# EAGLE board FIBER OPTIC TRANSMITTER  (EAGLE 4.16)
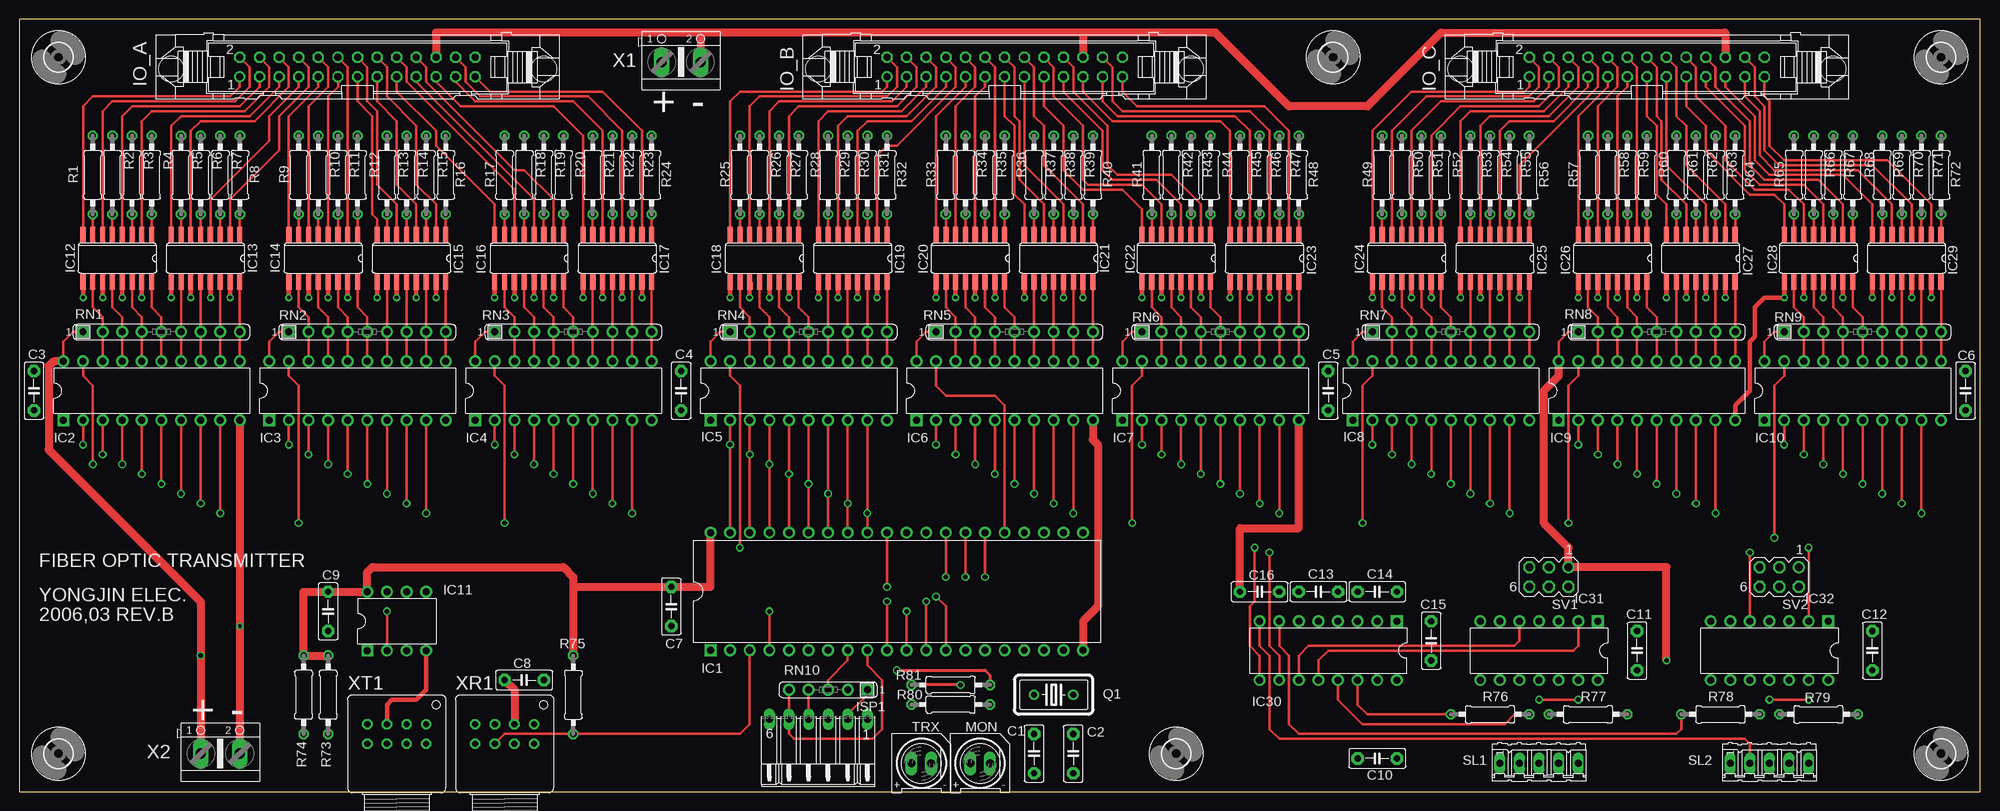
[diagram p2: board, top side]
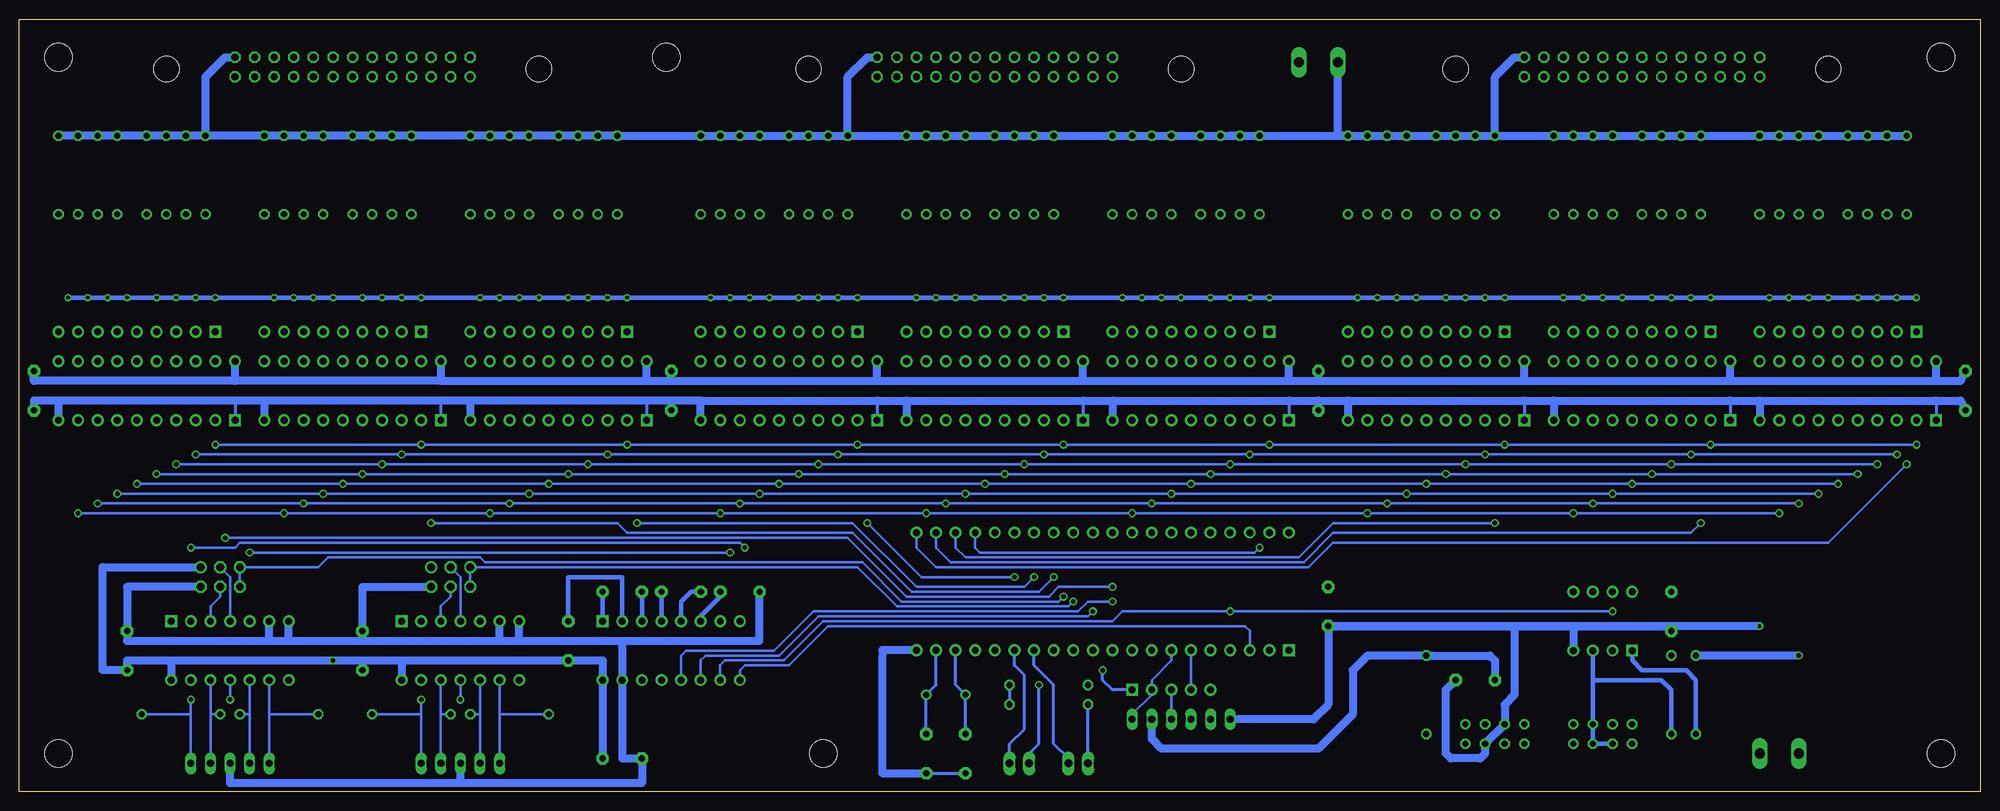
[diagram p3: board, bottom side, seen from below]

Size 253.99 x 100 mm. Coordinates in mm from the lower left corner, seen from the top.
Outline: 0,0 253.99,0 253.99,100 0,100 0,0
Copper layers (1*16): Top 0.035mm / dielectric 1.5mm / Bottom 0.035mm
Design rules "default": minimum track width 10mil, minimum drill 24mil, track to track 8mil, track to pad 8mil, pad to pad 8mil, via to via 8mil, smd to smd 8mil, copper to edge 40mil, drill to drill 8mil, minimum pad ring 10mil, minimum via ring 8mil, stop-mask expansion 4mil, vias tented up to drill 0mil, thermal gap 10mil

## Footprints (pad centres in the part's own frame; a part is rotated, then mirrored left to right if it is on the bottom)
C5B2.5 = drill 0.813 pad 1.6 octagon: 1 -2.54,0; 2 2.54,0
3,6 = hole 3.6: 0,0
DIL40 = drill 0.9 pad 1.524 square: 1 -24.13,-7.62 | drill 0.9 pad 1.524 round: 2 -21.59,-7.62; 3 -19.05,-7.62; 4 -16.51,-7.62; 5 -13.97,-7.62; 6 -11.43,-7.62; 7 -8.89,-7.62; 8 -6.35,-7.62; 9 -3.81,-7.62; 10 -1.27,-7.62; 11 1.27,-7.62; 12 3.81,-7.62; 13 6.35,-7.62; 14 8.89,-7.62; 15 11.43,-7.62; 16 13.97,-7.62; 17 16.51,-7.62; 18 19.05,-7.62; 19 21.59,-7.62; 20 24.13,-7.62; 21 24.13,7.62; 22 21.59,7.62; 23 19.05,7.62; 24 16.51,7.62; 25 13.97,7.62; 26 11.43,7.62; 27 8.89,7.62; 28 6.35,7.62; 29 3.81,7.62; 30 1.27,7.62; 31 -1.27,7.62; 32 -3.81,7.62; 33 -6.35,7.62; 34 -8.89,7.62; 35 -11.43,7.62; 36 -13.97,7.62; 37 -16.51,7.62; 38 -19.05,7.62; 39 -21.59,7.62; 40 -24.13,7.62
DIL20 = drill 0.9 pad 1.524 square: 1 -11.43,-3.81 | drill 0.9 pad 1.524 round: 2 -8.89,-3.81; 3 -6.35,-3.81; 4 -3.81,-3.81; 5 -1.27,-3.81; 6 1.27,-3.81; 7 3.81,-3.81; 8 6.35,-3.81; 9 8.89,-3.81; 10 11.43,-3.81; 11 11.43,3.81; 12 8.89,3.81; 13 6.35,3.81; 14 3.81,3.81; 15 1.27,3.81; 16 -1.27,3.81; 17 -3.81,3.81; 18 -6.35,3.81; 19 -8.89,3.81; 20 -11.43,3.81
DIL08 = drill 0.9 pad 1.524 square: 1 -3.81,-5.08 | drill 0.9 pad 1.524 round: 2 -1.27,-5.08; 3 1.27,-5.08; 4 3.81,-5.08; 5 3.81,2.54; 6 1.27,2.54; 7 -1.27,2.54; 8 -3.81,2.54
SOIC16 = smd 0.66 x 2.032: 1 -4.445,-3.073; 2 -3.175,-3.073; 3 -1.905,-3.073; 4 -0.635,-3.073; 5 0.635,-3.073; 6 1.905,-3.073; 7 3.175,-3.073; 8 4.445,-3.073; 9 4.445,3.073; 10 3.175,3.073; 11 1.905,3.073; 12 0.635,3.073; 13 -0.635,3.073; 14 -1.905,3.073; 15 -3.175,3.073; 16 -4.445,3.073
DIL16 = drill 0.9 pad 1.524 square: 1 -8.89,-3.81 | drill 0.9 pad 1.524 round: 2 -6.35,-3.81; 3 -3.81,-3.81; 4 -1.27,-3.81; 5 1.27,-3.81; 6 3.81,-3.81; 7 6.35,-3.81; 8 8.89,-3.81; 9 8.89,3.81; 10 6.35,3.81; 11 3.81,3.81; 12 1.27,3.81; 13 -1.27,3.81; 14 -3.81,3.81; 15 -6.35,3.81; 16 -8.89,3.81
DIL14 = drill 0.9 pad 1.524 square: 1 -7.62,-3.81 | drill 0.9 pad 1.524 round: 2 -5.08,-3.81; 3 -2.54,-3.81; 4 0,-3.81; 5 2.54,-3.81; 6 5.08,-3.81; 7 7.62,-3.81; 8 7.62,3.81; 9 5.08,3.81; 10 2.54,3.81; 11 0,3.81; 12 -2.54,3.81; 13 -5.08,3.81; 14 -7.62,3.81
26V = drill 0.914 round: 1 -15.24,-1.27 | drill 0.914 octagon: 2 -15.24,1.27; 3 -12.7,-1.27; 4 -12.7,1.27; 5 -10.16,-1.27; 6 -10.16,1.27; 7 -7.62,-1.27; 8 -7.62,1.27; 9 -5.08,-1.27; 10 -5.08,1.27; 11 -2.54,-1.27; 12 -2.54,1.27; 13 0,-1.27; 14 0,1.27; 15 2.54,-1.27; 16 2.54,1.27; 17 5.08,-1.27; 18 5.08,1.27; 19 7.62,-1.27; 20 7.62,1.27; 21 10.16,-1.27; 22 10.16,1.27; 23 12.7,-1.27; 24 12.7,1.27; 25 15.24,-1.27; 26 15.24,1.27 | hole 3.302: 24.13,-0.254; -24.13,-0.254
06PA = drill 0.914 long: 1 -6.35,0; 2 -3.81,0; 3 -1.27,0; 4 1.27,0; 5 3.81,0; 6 6.35,0
Q62902-B156 = drill 1.016 long: A -1.27,0; K 1.27,0
HC18U-V = drill 0.813 round: 1 -2.54,0; 2 2.54,0
0207/10 = drill 0.813 octagon: 1 -5.08,0; 2 5.08,0
SIL9 = drill 0.9 pad 1.524 square: 1 -10.16,0 | drill 0.9 pad 1.524 round: 2 -7.62,0; 3 -5.08,0; 4 -2.54,0; 5 0,0; 6 2.54,0; 7 5.08,0; 8 7.62,0; 9 10.16,0
SIL5 = drill 0.9 pad 1.524 square: 1 -5.08,0 | drill 0.9 pad 1.524 round: 2 -2.54,0; 3 0,0; 4 2.54,0; 5 5.08,0
05P = drill 0.914 long: 1 -5.08,0; 2 -2.54,0; 3 0,0; 4 2.54,0; 5 5.08,0
MA03-2 = drill 1.016 round: 1 -2.54,-1.27 | drill 1.016 octagon: 2 -2.54,1.27; 3 0,-1.27; 4 0,1.27; 5 2.54,-1.27; 6 2.54,1.27
AK500/2 = drill 1.321 long: 1 -2.515,0; 2 2.515,0
HFBR-X41XT = drill 0.813 round: 1 3.81,2.54 | drill 0.813 octagon: 2 1.27,2.54; 3 -1.27,2.54; 4 -3.81,2.54; 5 -3.81,0; 6 -1.27,0; 7 1.27,0; 8 3.81,0

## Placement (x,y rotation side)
C1  [C5B2.5]  131.44,4.92 90 top
C2  [C5B2.5]  136.52,4.92 90 top
C3  [C5B2.5]  1.9,51.91 270 top
C4  [C5B2.5]  85.72,51.91 270 top
C5  [C5B2.5]  169.54,51.91 270 top
C6  [C5B2.5]  252.09,51.91 270 top
C7  [C5B2.5]  84.45,23.96 270 top
C8  [C5B2.5]  65.4,14.44 0 top
C9  [C5B2.5]  40,23.33 270 top
C10  [C5B2.5]  175.89,4.28 180 top
C11  [C5B2.5]  209.55,18.25 90 top
C12  [C5B2.5]  240.03,18.25 90 top
C13  [C5B2.5]  168.27,25.87 180 top
C14  [C5B2.5]  175.89,25.87 180 top
C15  [C5B2.5]  182.88,19.52 270 top
C16  [C5B2.5]  160.65,25.87 0 top
H1  MOUNT-HOLE3.6  [3,6]  5.08,4.92 0 top
H2  MOUNT-HOLE3.6  [3,6]  5.08,95.08 0 top
H3  MOUNT-HOLE3.6  [3,6]  149.86,4.92 0 top
H4  MOUNT-HOLE3.6  [3,6]  170.18,95.08 0 top
H5  MOUNT-HOLE3.6  [3,6]  248.91,4.92 0 top
H6  MOUNT-HOLE3.6  [3,6]  248.91,95.08 0 top
IC1  MEGA161P  [DIL40]  113.66,25.92 0 top
IC2  74HC245N  [DIL20]  17.14,51.91 0 top
IC3  74HC245N  [DIL20]  43.81,51.91 0 top
IC4  74HC245N  [DIL20]  70.48,51.91 0 top
IC5  74HC245N  [DIL20]  100.96,51.91 0 top
IC6  74HC245N  [DIL20]  127.63,51.91 0 top
IC7  74HC245N  [DIL20]  154.3,51.91 0 top
IC8  74HC245N  [DIL20]  184.15,51.91 0 top
IC9  74HC245N  [DIL20]  210.81,51.91 0 top
IC10  74HC245N  [DIL20]  237.49,51.91 0 top
IC11  75452  [DIL08]  48.89,23.33 0 top
IC12  TCMT4100  [SOIC16]  12.69,69.05 180 top
IC13  TCMT4100  [SOIC16]  24.12,69.05 180 top
IC14  TCMT4100  [SOIC16]  39.36,69.05 180 top
IC15  TCMT4100  [SOIC16]  50.79,69.05 180 top
IC16  TCMT4100  [SOIC16]  66.04,69.05 180 top
IC17  TCMT4100  [SOIC16]  77.47,69.05 180 top
IC18  TCMT4100  [SOIC16]  96.52,69.05 180.1 top
IC19  TCMT4100  [SOIC16]  107.95,69.05 180 top
IC20  TCMT4100  [SOIC16]  123.19,69.05 180 top
IC21  TCMT4100  [SOIC16]  134.62,69.05 180 top
IC22  TCMT4100  [SOIC16]  149.86,69.05 180 top
IC23  TCMT4100  [SOIC16]  161.28,69.05 180 top
IC24  TCMT4100  [SOIC16]  179.7,69.05 180 top
IC25  TCMT4100  [SOIC16]  191.13,69.05 180 top
IC26  TCMT4100  [SOIC16]  206.37,69.05 180 top
IC27  TCMT4100  [SOIC16]  217.8,69.05 180 top
IC28  TCMT4100  [SOIC16]  233.04,69.05 180 top
IC29  TCMT4100  [SOIC16]  244.47,69.05 180 top
IC30  MAX232  [DIL16]  169.54,18.25 180 top
IC31  MAX489CPD  [DIL14]  196.84,18.25 180 top
IC32  MAX489CPD  [DIL14]  226.69,18.25 180 top
IO_A  [26V]  43.81,93.81 0 top
IO_B  [26V]  127.63,93.81 0 top
IO_C  [26V]  210.81,93.81 0 top
ISP1  [06PA]  103.5,9.36 180 top
MON  [Q62902-B156]  124.45,3.65 0 top
Q1  [HC18U-V]  133.98,12.54 180 top
R1  [0207/10]  9.52,79.84 270 top
R2  [0207/10]  12.06,79.84 270 top
R3  [0207/10]  14.6,79.84 270 top
R4  [0207/10]  17.14,79.84 270 top
R5  [0207/10]  20.95,79.84 270 top
R6  [0207/10]  23.49,79.84 270 top
R7  [0207/10]  26.03,79.84 270 top
R8  [0207/10]  28.57,79.84 270 top
R9  [0207/10]  36.19,79.84 270 top
R10  [0207/10]  38.73,79.84 270 top
R11  [0207/10]  41.27,79.84 270 top
R12  [0207/10]  43.81,79.84 270 top
R13  [0207/10]  47.62,79.84 270 top
R14  [0207/10]  50.16,79.84 270 top
R15  [0207/10]  52.7,79.84 270 top
R16  [0207/10]  55.24,79.84 270 top
R17  [0207/10]  62.86,79.84 270 top
R18  [0207/10]  65.4,79.84 270 top
R19  [0207/10]  67.94,79.84 270 top
R20  [0207/10]  70.48,79.84 270 top
R21  [0207/10]  74.29,79.84 270 top
R22  [0207/10]  76.83,79.84 270 top
R23  [0207/10]  79.37,79.84 270 top
R24  [0207/10]  81.91,79.84 270 top
R25  [0207/10]  93.34,79.84 270 top
R26  [0207/10]  95.88,79.84 270 top
R27  [0207/10]  98.42,79.84 270 top
R28  [0207/10]  100.96,79.84 270 top
R29  [0207/10]  104.77,79.84 270 top
R30  [0207/10]  107.31,79.84 270 top
R31  [0207/10]  109.85,79.84 270 top
R32  [0207/10]  112.39,79.84 270 top
R33  [0207/10]  120.01,79.84 270 top
R34  [0207/10]  122.55,79.84 270 top
R35  [0207/10]  125.09,79.84 270 top
R36  [0207/10]  127.63,79.84 270 top
R37  [0207/10]  131.44,79.84 270 top
R38  [0207/10]  133.98,79.84 270 top
R39  [0207/10]  136.52,79.84 270 top
R40  [0207/10]  139.06,79.84 270 top
R41  [0207/10]  146.68,79.84 270 top
R42  [0207/10]  149.22,79.84 270 top
R43  [0207/10]  151.76,79.84 270 top
R44  [0207/10]  154.3,79.84 270 top
R45  [0207/10]  158.11,79.84 270 top
R46  [0207/10]  160.65,79.84 270 top
R47  [0207/10]  163.19,79.84 270 top
R48  [0207/10]  165.73,79.84 270 top
R49  [0207/10]  176.53,79.84 270 top
R50  [0207/10]  179.06,79.84 270 top
R51  [0207/10]  181.61,79.84 270 top
R52  [0207/10]  184.15,79.84 270 top
R53  [0207/10]  187.96,79.84 270 top
R54  [0207/10]  190.5,79.84 270 top
R55  [0207/10]  193.03,79.84 270 top
R56  [0207/10]  195.58,79.84 270 top
R57  [0207/10]  203.19,79.84 270 top
R58  [0207/10]  205.74,79.84 270 top
R59  [0207/10]  208.28,79.84 270 top
R60  [0207/10]  210.81,79.84 270 top
R61  [0207/10]  214.62,79.84 270 top
R62  [0207/10]  217.16,79.84 270 top
R63  [0207/10]  219.71,79.84 270 top
R64  [0207/10]  222.25,79.84 270 top
R65  [0207/10]  229.87,79.84 270 top
R66  [0207/10]  232.41,79.84 270 top
R67  [0207/10]  234.94,79.84 270 top
R68  [0207/10]  237.49,79.84 270 top
R69  [0207/10]  241.3,79.84 270 top
R70  [0207/10]  243.84,79.84 270 top
R71  [0207/10]  246.38,79.84 270 top
R72  [0207/10]  248.91,79.84 270 top
R73  [0207/10]  40,12.54 90 top
R74  [0207/10]  36.82,12.54 90 top
R75  [0207/10]  71.75,12.54 270 top
R76  [0207/10]  190.5,10 180 top
R77  [0207/10]  203.19,10 180 top
R78  [0207/10]  220.34,10 180 top
R79  [0207/10]  233.04,10 180 top
R80  [0207/10]  120.65,11.27 0 top
R81  [0207/10]  120.65,13.81 0 top
RN1  [SIL9]  18.41,59.52 0 top
RN2  [SIL9]  45.08,59.52 0 top
RN3  [SIL9]  71.75,59.52 0 top
RN4  [SIL9]  102.23,59.52 0 top
RN5  [SIL9]  128.9,59.52 0 top
RN6  [SIL9]  155.57,59.52 0 top
RN7  [SIL9]  185.41,59.52 0 top
RN8  [SIL9]  212.09,59.52 0 top
RN9  [SIL9]  238.75,59.52 0 top
RN10  [SIL5]  104.77,13.17 180 top
SL1  [05P]  196.84,3.65 0 top
SL2  [05P]  226.69,3.65 0 top
SV1  [MA03-2]  198.12,27.78 180 top
SV2  [MA03-2]  227.96,27.78 180 top
TRX  [Q62902-B156]  116.84,3.65 0 top
X1  [AK500/2]  85.72,94.45 0 top
X2  [AK500/2]  26.03,4.92 0 top
XR1  2412T  [HFBR-X41XT]  62.86,6.18 0 top
XT1  1412T  [HFBR-X41XT]  48.89,6.18 0 top

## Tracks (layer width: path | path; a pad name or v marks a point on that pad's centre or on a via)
+12V
  Bottom 1.016: R1.1 R2.1 R3.1 R4.1 R5.1 R6.1 R7.1 R8.1 R9.1 R10.1 R11.1 R12.1 R13.1 R14.1 R15.1 R16.1 R17.1 | R19.1 R18.1 | R20.1 R19.1 | R21.1 R20.1 | R22.1 R21.1 | R23.1 R22.1 | R24.1 R23.1 | R18.1 R17.1 | R18.1 R17.1 | R19.1 R18.1 | R20.1 R19.1 | R21.1 R20.1 | R22.1 R21.1 | R23.1 R22.1 | R24.1 R23.1 | R25.1 R24.1 | R26.1 R25.1 | 96.52,84.92 R26.1 | 96.52,84.92 97.15,84.92 | R27.1 96.52,84.92 | R27.1 R26.1 | R27.1 R28.1 R29.1 R30.1 R31.1 R32.1 | R27.1 R25.1 | R32.1 113.03,84.92 | R32.1 R33.1 R34.1 R35.1 R36.1 R37.1 R38.1 R39.1 R40.1 R41.1 | R41.1 R42.1 R43.1 R44.1 R45.1 R46.1 R47.1 R48.1 R49.1 R50.1 R51.1 R52.1 R53.1 R54.1 R55.1 R56.1 R57.1 R58.1 R59.1 R60.1 R61.1 R62.1 R63.1 R64.1 R65.1 | R65.1 R66.1 R67.1 R68.1 R69.1 R70.1 R71.1 R72.1 | IO_C.26 227.33,95.08 229.87,92.54 R65.1 | IO_A.26 60.32,95.08 62.86,92.54 R17.1 | IO_B.26 144.14,95.08 146.68,92.54 R41.1 | X1.1 83.18,84.9 R24.1
-12V
  Top 1.016: IO_C.22 220.97,98.26 184.15,98.26 174.62,88.73 164.46,88.73 154.94,98.26 137.79,98.26 | 137.79,98.26 IO_B.22 | 137.79,98.26 88.26,98.26 | 88.26,98.26 53.97,98.26 IO_A.22 | X1.2 88.26,94.47 88.26,98.26
/RST
  Top 0.305: RN10.5 ISP1.5 99.69,7.46 100.33,6.82 110.48,6.82 111.76,8.09 111.76,14.44 109.85,16.35 IC1.9
BD0  (via drill 0.6)
  Top 0.305: v8.25,44.92 IC2.2 | v34.92,44.92 IC3.2 | v34.92,44.92 IC3.2 | v228.59,44.92 IC10.2 | v34.92,44.92 IC3.2 | v61.59,44.92 IC4.2 | IC1.39 v92.07,44.92 IC5.2 | v145.41,44.92 IC7.2 | v175.25,44.92 IC8.2 | v201.93,44.92 IC9.2 | v118.74,44.92 IC6.2 v118.74,44.92
  Bottom 0.305: v8.25,44.92 v34.92,44.92 v61.59,44.92 v92.07,44.92 | v228.59,44.92 v201.93,44.92 v175.25,44.92 v145.41,44.92 v118.74,44.92 | v118.74,44.92 v92.07,44.92 | v118.74,44.92 v92.07,44.92
BD1  (via drill 0.6)
  Top 0.305: v10.79,43.65 IC2.3 | v37.46,43.65 IC3.3 | v231.13,43.65 IC10.3 | v64.13,43.65 IC4.3 | IC5.3 v94.61,43.65 IC1.38 | v147.95,43.65 IC7.3 | v177.8,43.65 IC8.3 | v204.47,43.65 IC9.3 | v121.28,43.65 IC6.3 v121.28,43.65
  Bottom 0.305: v37.46,43.65 v10.79,43.65 | v231.13,43.65 v204.47,43.65 v177.8,43.65 v147.95,43.65 v121.28,43.65 | v94.61,43.65 v64.13,43.65 | v64.13,43.65 v37.46,43.65 | v64.13,43.65 v37.46,43.65 | v121.28,43.65 v94.61,43.65 | v121.28,43.65 v94.61,43.65
BD2  (via drill 0.6)
  Top 0.305: v13.33,42.38 IC2.4 | v40,42.38 IC3.4 | v233.68,42.38 IC10.4 | v66.67,42.38 IC4.4 | IC5.4 v97.15,42.38 IC1.37 | v123.82,42.38 IC6.4 | v150.49,42.38 IC7.4 | v180.34,42.38 IC8.4 | IC9.4 v207,42.38
  Bottom 0.305: v40,42.38 v13.33,42.38 | v233.68,42.38 v207,42.38 v180.34,42.38 v150.49,42.38 | v66.67,42.38 v97.15,42.38 v123.82,42.38 | v66.67,42.38 v40,42.38 | v66.67,42.38 v40,42.38 | v150.49,42.38 v123.82,42.38 | v150.49,42.38 v123.82,42.38
BD3  (via drill 0.6)
  Top 0.305: v15.87,41.11 IC2.5 | v42.54,41.11 IC3.5 | IC5.5 v99.69,41.11 IC1.36 | v236.22,41.11 IC10.5 | v126.36,41.11 IC6.5 | v153.03,41.11 IC7.5 | v182.88,41.11 IC8.5 | IC9.5 v209.55,41.11 | v69.21,41.11 IC4.5 v69.21,41.11
  Bottom 0.305: v15.87,41.11 v42.54,41.11 v69.21,41.11 v99.69,41.11 v126.36,41.11 | v236.22,41.11 v209.55,41.11 v182.88,41.11 v153.03,41.11 | v153.03,41.11 v126.36,41.11 | v153.03,41.11 v126.36,41.11
BD4  (via drill 0.6)
  Top 0.305: v18.41,39.84 IC2.6 | v45.08,39.84 IC3.6 | v102.23,39.84 IC1.35 | v102.23,39.84 IC5.6 v102.23,39.84 | IC1.35 102.23,33.49 | v102.23,39.84 IC1.35 | IC9.6 v212.09,39.84 | v238.75,39.84 IC10.6 | v71.75,39.84 IC4.6 v71.75,39.84 | v128.9,39.84 IC6.6 v128.9,39.84 | v155.57,39.84 IC7.6 v155.57,39.84 | v185.41,39.84 IC8.6 v185.41,39.84
  Bottom 0.305: v18.41,39.84 v45.08,39.84 v71.75,39.84 v102.23,39.84 v128.9,39.84 v155.57,39.84 v185.41,39.84 v212.09,39.84 v238.75,39.84
BD5  (via drill 0.6)
  Top 0.305: v20.95,38.57 IC2.7 | v47.62,38.57 IC3.7 | v104.77,38.57 IC1.34 | v104.77,38.57 IC5.7 v104.77,38.57 | IC1.34 104.77,33.49 | v104.77,38.57 IC1.34 | IC9.7 v214.62,38.57 | v241.3,38.57 IC10.7 | v74.29,38.57 IC4.7 v74.29,38.57 | v131.44,38.57 IC6.7 v131.44,38.57 | v158.11,38.57 IC7.7 v158.11,38.57 | v187.96,38.57 IC8.7 v187.96,38.57
  Bottom 0.305: v20.95,38.57 v47.62,38.57 v74.29,38.57 v104.77,38.57 v131.44,38.57 v158.11,38.57 v187.96,38.57 v214.62,38.57 v241.3,38.57
BD6  (via drill 0.6)
  Top 0.305: v23.49,37.3 IC2.8 | v76.83,37.3 IC4.8 | v76.83,37.3 IC4.8 | v107.31,37.3 IC1.33 | v107.31,37.3 IC5.8 v107.31,37.3 | v76.83,37.3 IC4.8 | IC1.33 107.31,33.49 | v107.31,37.3 IC1.33 | IC9.8 v217.16,37.3 | v243.84,37.3 IC10.8 | v50.16,37.3 IC3.8 v50.16,37.3 | v133.98,37.3 IC6.8 v133.98,37.3 | v160.65,37.3 IC7.8 v160.65,37.3 | v190.5,37.3 IC8.8 v190.5,37.3
  Bottom 0.305: v23.49,37.3 v50.16,37.3 v76.83,37.3 v107.31,37.3 v133.98,37.3 v160.65,37.3 v190.5,37.3 v217.16,37.3 v243.84,37.3 | IC1.33 107.31,33.49
BD7  (via drill 0.6)
  Top 0.305: v26.03,36.03 IC2.9 | v109.85,36.03 IC1.32 | v109.85,36.03 IC5.9 v109.85,36.03 | IC1.32 109.85,33.49 | v109.85,36.03 IC1.32 | v219.71,36.03 IC9.9 | v246.38,36.03 IC10.9 | v52.7,36.03 IC3.9 v52.7,36.03 | v79.37,36.03 IC4.9 v79.37,36.03 | v136.52,36.03 IC6.9 v136.52,36.03 | v163.19,36.03 IC7.9 v163.19,36.03 | v193.03,36.03 IC8.9 v193.03,36.03
  Bottom 0.305: v26.03,36.03 v52.7,36.03 v79.37,36.03 v109.85,36.03 v136.52,36.03 v163.19,36.03 v193.03,36.03 v219.71,36.03 v246.38,36.03
GND5  (via drill 0.5)
  Top 0.61: XT1.3 47.62,11.27 48.25,11.9 51.43,11.9 52.7,13.17 IC11.4 | v8.25,63.97 IC12.9 | v10.79,63.97 IC12.11 | v13.33,63.97 IC12.13 | v15.87,63.97 IC12.15 | v19.68,63.97 IC13.9 | v22.22,63.97 IC13.11 | v24.76,63.97 IC13.13 | v27.3,63.97 IC13.15 | v34.92,63.97 IC14.9 | v37.46,63.97 IC14.11 | v40,63.97 IC14.13 | v42.54,63.97 IC14.15 | v46.35,63.97 IC15.9 | v48.89,63.97 IC15.11 | v51.43,63.97 IC15.13 | v53.97,63.97 IC15.15 | v61.59,63.97 IC16.9 | v64.13,63.97 IC16.11 | v66.67,63.97 IC16.13 | v69.21,63.97 IC16.15 | v73.02,63.97 IC17.9 | v75.56,63.97 IC17.11 | v78.1,63.97 IC17.13 | v80.64,63.97 IC17.15 | v103.5,63.97 IC19.9 | v106.04,63.97 IC19.11 | v108.58,63.97 IC19.13 | v111.12,63.97 IC19.15 | v118.74,63.97 IC20.9 | v121.28,63.97 IC20.11 | v123.82,63.97 IC20.13 | v126.36,63.97 IC20.15 | v130.17,63.97 IC21.9 | v132.71,63.97 IC21.11 | v135.25,63.97 IC21.13 | v137.79,63.97 IC21.15 | v145.41,63.97 IC22.9 | v147.95,63.97 IC22.11 | v150.49,63.97 IC22.13 | v153.03,63.97 IC22.15 | v156.84,63.97 IC23.9 | v159.38,63.97 IC23.11 | v161.92,63.97 IC23.13 | v164.46,63.97 IC23.15 | v175.25,63.97 IC24.9 | v177.8,63.97 IC24.11 | v180.34,63.97 IC24.13 | v182.88,63.97 IC24.15 | v186.69,63.97 IC25.9 | v189.22,63.97 IC25.11 | v191.77,63.97 IC25.13 | v194.31,63.97 IC25.15 | v201.93,63.97 IC26.9 | v204.47,63.97 IC26.11 | v207,63.97 IC26.13 | v209.55,63.97 IC26.15 | v213.36,63.97 IC27.9 | v215.9,63.97 IC27.11 | v218.44,63.97 IC27.13 | v220.97,63.97 IC27.15 | IC28.9 v228.59,63.97 226.06,63.97 224.78,62.7 224.78,58.89 224.15,58.26 224.15,51.91 222.25,50 IC9.10 | v231.13,63.97 IC28.11 | v233.68,63.97 IC28.13 | v236.22,63.97 IC28.15 | v240.03,63.97 IC29.9 | v242.56,63.97 IC29.11 | v245.11,63.97 IC29.13 | v247.65,63.97 IC29.15
  Top 0.61: 92.07,65.88 92.08,65.88 IC18.9 v92.08,63.98 v92.07,63.97 92.07,65.88 | 94.61,65.88 94.62,65.88 IC18.11 v94.62,63.98 v94.61,63.97 94.61,65.88 | 97.15,65.88 97.16,65.88 IC18.13 v97.16,63.98 v97.15,63.97 97.15,65.88 | 99.69,65.88 99.7,65.88 IC18.15 v99.7,63.98 v99.69,63.97 99.69,65.88
  Top 1.016: IC2.10 v28.57,21.43 28.57,4.92 X2.2 | IC6.10 139.06,45.55 139.69,44.92 139.69,23.96 137.79,22.06 IC1.20 137.79,18.25 | C16.1 158.11,34.12 165.73,34.12 IC7.10
  Bottom 0.406: C2.1 C1.1 | 226.06,50.63 IC10.1 | 199.38,50.63 IC9.1 | 172.72,50.63 IC8.1 | 142.87,50.63 IC7.1 | 116.2,50.63 IC6.1 | 89.53,50.63 IC5.1 | 59.05,50.63 IC4.1 | 32.38,50.63 IC3.1 | 5.71,50.63 IC2.1
  Bottom 0.61: v8.25,63.97 v10.79,63.97 v13.33,63.97 v15.87,63.97 v19.68,63.97 v22.22,63.97 v24.76,63.97 v27.3,63.97 v34.92,63.97 v37.46,63.97 v40,63.97 v42.54,63.97 v46.35,63.97 v48.89,63.97 v51.43,63.97 v53.97,63.97 v61.59,63.97 v64.13,63.97 v66.67,63.97 v69.21,63.97 v73.02,63.97 v75.56,63.97 v78.1,63.97 v80.64,63.97 v92.07,63.97 v94.61,63.97 v97.15,63.97 v99.69,63.97 v103.5,63.97 v106.04,63.97 v108.58,63.97 v111.12,63.97 v118.74,63.97 v121.28,63.97 v123.82,63.97 v126.36,63.97 v130.17,63.97 v132.71,63.97 v135.25,63.97 v137.79,63.97 v145.41,63.97 v147.95,63.97 v150.49,63.97 v153.03,63.97 v156.84,63.97 v159.38,63.97 v161.92,63.97 v164.46,63.97 v175.25,63.97 v177.8,63.97 v180.34,63.97 v182.88,63.97 v186.69,63.97 v189.22,63.97 v191.77,63.97 v194.31,63.97 v201.93,63.97 v204.47,63.97 v207,63.97 v209.55,63.97 v213.36,63.97 v215.9,63.97 v218.44,63.97 v220.97,63.97 v228.59,63.97 v231.13,63.97 v233.68,63.97 v236.22,63.97 v240.03,63.97 v242.56,63.97 v245.11,63.97 v247.65,63.97 | 186.05,50.63 199.38,50.63 221.61,50.63 222.25,50
  Bottom 1.016: 52.7,21.43 40,21.43 C9.2 | 60.32,21.43 52.7,21.43 | C7.2 60.32,21.43 | C7.2 84.45,11.27 86.36,9.36 ISP1.6 | 52.7,21.43 IC11.4 | 60.32,21.43 60.32,12.54 61.59,11.27 XR1.3 XR1.7 64.13,4.92 64.77,4.28 68.58,4.28 69.21,4.92 69.21,13.17 C8.2 | C6.2 252.09,50.63 248.91,50.63 | 248.91,50.63 IC10.10 | 222.25,50.63 226.06,50.63 248.91,50.63 | IC9.10 222.25,50 222.25,50.63 | 195.58,50.63 199.38,50.63 222.25,50.63 | 195.58,50.63 IC8.10 | 195.58,50.63 186.05,50.63 172.72,50.63 169.54,50.63 | 169.54,50.63 C5.2 | 165.73,50.63 169.54,50.63 | IC7.10 165.73,50.63 | 165.73,50.63 142.87,50.63 139.06,50.63 | 139.06,50.63 IC6.10 | 139.06,50.63 116.2,50.63 112.39,50.63 | 112.39,50.63 IC5.10 | 112.39,50.63 89.53,50.63 85.72,50.63 | 85.72,50.63 C4.2 | 85.72,50.63 81.91,50.63 | 81.91,50.63 IC4.10 | 81.91,50.63 59.05,50.63 55.24,50.63 | 55.24,50.63 IC3.10 | 28.57,50.63 IC2.10 | 55.24,50.63 32.38,50.63 28.57,50.63 | C3.2 2.54,50.63 5.71,50.63 28.57,50.63 | v28.57,21.43 C7.2 | IC1.20 142.19,18.3 142.24,16.98 142.24,2.38 C2.1 | 221.61,19.52 240.03,19.52 C12.2 240.03,26.51 SV2.2 | 221.61,19.52 IC32.6 | 175.89,19.52 IC30.15 175.89,4.28 C10.2 173.35,1.1 196.84,1.1 | 189.22,19.52 175.89,19.52 | 189.22,19.52 IC31.7 | 191.77,19.52 189.22,19.52 | 191.77,19.52 IC31.6 | 209.55,19.52 191.77,19.52 | 209.55,19.52 C11.2 209.55,26.51 SV1.2 | 219.07,19.52 209.55,19.52 | 219.07,19.52 IC32.7 | 221.61,19.52 219.07,19.52 | 196.84,1.1 SL1.3 | SL2.3 226.69,1.1 196.84,1.1 | C16.1 158.11,19.52 175.89,19.52
I_A0
  Top 0.305: IC12.8 8.25,88.73 9.52,90 27.3,90 28.57,91.27 IO_A.1
I_A1
  Top 0.305: IC12.6 10.79,88.1 12.06,89.37 27.94,89.37 29.84,91.27 29.84,93.81 IO_A.2
I_A2
  Top 0.305: IC12.4 13.33,87.46 14.6,88.73 28.57,88.73 31.11,91.27 IO_A.3
I_A3
  Top 0.305: IC12.2 15.87,86.83 17.14,88.1 29.21,88.1 32.38,91.27 32.38,93.81 IO_A.4
I_A4
  Top 0.305: IC13.8 19.68,86.19 20.95,87.46 29.84,87.46 33.65,91.27 IO_A.5
I_A5
  Top 0.305: IC13.6 22.22,85.56 23.49,86.83 30.48,86.83 34.92,91.27 34.92,93.81 IO_A.6
I_A6
  Top 0.305: IC13.4 24.76,76.67 32.38,84.29 32.38,87.46 36.19,91.27 IO_A.7
I_A7
  Top 0.305: IC13.2 27.3,76.67 33.65,83.02 33.65,87.46 37.46,91.27 37.46,93.81 IO_A.8
I_A8
  Top 0.305: IC14.8 34.92,87.46 38.73,91.27 IO_A.9
I_A9
  Top 0.305: IC14.6 37.46,88.73 40,91.27 40,93.81 IO_A.10
I_A10
  Top 0.305: IC14.4 40,90 41.27,91.27 IO_A.11
I_A11
  Top 0.305: IC14.2 42.54,93.81 IO_A.12
I_A12
  Top 0.305: IC15.8 46.35,74.13 45.71,74.77 45.71,87.46 43.81,89.37 IO_A.13
I_A13
  Top 0.305: IC15.6 48.89,76.03 46.35,78.57 46.35,88.1 45.08,89.37 45.08,93.81 IO_A.14
I_A14
  Top 0.305: IC15.4 51.43,76.03 48.89,78.57 48.89,86.83 46.35,89.37 IO_A.15
I_A15
  Top 0.305: IC15.2 53.97,76.03 51.43,78.57 51.43,86.19 47.62,90 47.62,93.81 IO_A.16
I_A16
  Top 0.305: IC16.8 61.59,76.03 53.97,83.65 53.97,85.56 48.89,90.64 IO_A.17
I_A17
  Top 0.305: IC16.6 64.13,77.94 50.16,91.91 50.16,93.81 IO_A.18
I_A18
  Top 0.305: IC16.4 66.67,76.67 51.43,91.91 IO_A.19
I_A19
  Top 0.305: IC16.2 69.21,76.67 65.4,80.48 64.13,80.48 52.7,91.91 52.7,93.81 IO_A.20
I_A20
  Top 0.305: IC17.8 73.02,84.92 69.21,88.73 57.14,88.73 53.97,91.91 IO_A.21
I_A21
  Top 0.305: IC17.6 75.56,85.56 71.75,89.37 59.05,89.37 56.51,91.91 IO_A.23
I_A22
  Top 0.305: IC17.4 78.1,85.56 73.66,90 59.68,90 57.78,91.91 57.78,93.81 IO_A.24
I_A23
  Top 0.305: IC17.2 80.64,85.56 75.56,90.64 60.95,90.64 IO_A.25
I_B0
  Top 0.305: IC18.8 92.07,89.37 93.34,90.64 111.76,90.64 112.39,91.27 IO_B.1
I_B1
  Top 0.305: IC18.6 94.61,88.73 95.88,90 112.39,90 113.66,91.27 113.66,93.81 IO_B.2
I_B2
  Top 0.305: IC18.4 97.15,88.1 98.42,89.37 113.03,89.37 114.93,91.27 IO_B.3
I_B3
  Top 0.305: IC18.2 99.69,87.46 100.96,88.73 113.66,88.73 116.2,91.27 116.2,93.81 IO_B.4
I_B4
  Top 0.305: IC19.8 103.5,86.83 104.77,88.1 114.3,88.1 117.47,91.27 IO_B.5
I_B5
  Top 0.305: IC19.6 106.04,86.19 107.31,87.46 114.93,87.46 118.74,91.27 118.74,93.81 IO_B.6
I_B6
  Top 0.305: IC19.4 108.58,85.56 109.85,86.83 115.56,86.83 120.01,91.27 IO_B.7
I_B7
  Top 0.305: IC19.2 111.12,82.38 112.39,83.65 113.66,83.65 121.28,91.27 121.28,93.81 IO_B.8
I_B8
  Top 0.305: IC20.8 118.74,87.46 122.55,91.27 IO_B.9
I_B9
  Top 0.305: IC20.6 121.28,88.73 123.82,91.27 123.82,93.81 IO_B.10
I_B10
  Top 0.305: IC20.4 123.82,90 125.09,91.27 IO_B.11
I_B11
  Top 0.305: IC20.2 126.36,93.81 IO_B.12
I_B12
  Top 0.305: IC21.8 130.17,76.03 128.9,77.3 128.9,86.19 127.63,87.46 IO_B.13
I_B13
  Top 0.305: IC21.6 132.71,76.03 129.53,79.21 129.53,86.83 128.9,87.46 128.9,93.81 IO_B.14
I_B14
  Top 0.305: IC21.4 135.25,76.03 130.17,81.11 IO_B.15
I_B15
  Top 0.305: IC21.2 137.79,76.03 132.71,81.11 132.71,86.19 131.44,87.46 131.44,93.81 IO_B.16
I_B16
  Top 0.305: IC22.8 145.41,75.4 142.87,77.94 137.79,77.94 135.25,80.48 135.25,86.19 132.71,88.73 IO_B.17
I_B17
  Top 0.305: IC22.6 147.95,76.03 145.41,78.57 138.43,78.57 137.79,79.21 137.79,86.19 133.98,90 133.98,93.81 IO_B.18
I_B18
  Top 0.305: IC22.4 150.49,76.03 147.31,79.21 141.6,79.21 140.33,80.48 140.33,85.56 135.25,90.64 IO_B.19
I_B19
  Top 0.305: IC22.2 153.03,76.03 149.22,79.84 142.24,79.84 140.97,81.11 140.97,86.19 136.52,90.64 136.52,93.81 IO_B.20
I_B20
  Top 0.305: IC23.8 156.84,85.56 155.57,86.83 141.6,86.83 137.79,90.64 IO_B.21
I_B21
  Top 0.305: IC23.6 159.38,85.56 157.47,87.46 142.24,87.46 140.33,89.37 IO_B.23
I_B22
  Top 0.305: IC23.4 161.92,85.56 159.38,88.1 142.87,88.1 141.6,89.37 141.6,93.81 IO_B.24
I_B23
  Top 0.305: IC23.2 164.46,85.56 161.28,88.73 144.78,88.73 142.87,90.64 IO_B.25
I_C0
  Top 0.305: IC24.8 175.25,85.56 180.34,90.64 194.94,90.64 195.58,91.27 IO_C.1
I_C1
  Top 0.305: IC24.6 177.8,85.56 182.24,90 195.58,90 196.84,91.27 196.84,93.81 IO_C.2
I_C2
  Top 0.305: IC24.4 180.34,85.56 184.15,89.37 196.21,89.37 198.12,91.27 IO_C.3
I_C3
  Top 0.305: IC24.2 182.88,84.92 186.69,88.73 196.84,88.73 199.38,91.27 199.38,93.81 IO_C.4
I_C4
  Top 0.305: IC25.8 186.69,86.83 187.96,88.1 197.48,88.1 200.66,91.27 IO_C.5
I_C5
  Top 0.305: IC25.6 189.22,86.19 190.5,87.46 198.12,87.46 201.93,91.27 201.93,93.81 IO_C.6
I_C6
  Top 0.305: IC25.4 191.77,85.56 193.03,86.83 198.75,86.83 203.19,91.27 IO_C.7
I_C7
  Top 0.305: IC25.2 194.31,81.11 204.47,91.27 204.47,93.81 IO_C.8
I_C8
  Top 0.305: IC26.8 201.93,87.46 205.74,91.27 IO_C.9
I_C9
  Top 0.305: IC26.6 204.47,88.73 207,91.27 207,93.81 IO_C.10
I_C10
  Top 0.305: IC26.4 207,90 208.28,91.27 IO_C.11
I_C11
  Top 0.305: IC26.2 209.55,93.81 IO_C.12
I_C12
  Top 0.305: IC27.8 213.36,76.03 212.09,77.3 212.09,86.19 210.81,87.46 IO_C.13
I_C13
  Top 0.305: IC27.6 215.9,76.03 212.72,79.21 212.72,86.83 212.09,87.46 212.09,93.81 IO_C.14
I_C14
  Top 0.305: IC27.4 218.44,76.03 213.36,81.11 IO_C.15
I_C15
  Top 0.305: IC27.2 220.97,76.03 215.9,81.11 215.9,86.19 214.62,87.46 214.62,93.81 IO_C.16
I_C16
  Top 0.305: IC28.8 228.59,76.03 227.33,77.3 224.15,77.3 218.44,83.02 218.44,86.19 215.9,88.73 IO_C.17
I_C17
  Top 0.305: IC28.6 231.13,76.03 229.23,77.94 224.78,77.94 220.97,81.75 220.97,86.19 217.16,90 217.16,93.81 IO_C.18
I_C18
  Top 0.305: IC28.4 233.68,76.03 231.13,78.57 225.42,78.57 223.52,80.48 223.52,86.19 218.44,91.27 IO_C.19
I_C19
  Top 0.305: IC28.2 236.22,76.03 233.04,79.21 226.06,79.21 224.15,81.11 224.15,86.83 219.71,91.27 219.71,93.81 IO_C.20
I_C20
  Top 0.305: IC29.8 240.03,76.03 236.22,79.84 226.69,79.84 224.78,81.75 224.78,87.46 220.97,91.27 IO_C.21
I_C21
  Top 0.305: IC29.6 242.56,76.03 238.12,80.48 227.33,80.48 225.42,82.38 225.42,88.1 223.52,90 IO_C.23
I_C22
  Top 0.305: IC29.4 245.11,76.03 240.03,81.11 227.96,81.11 226.06,83.02 226.06,88.73 224.78,90 224.78,93.81 IO_C.24
I_C23
  Top 0.305: IC29.2 247.65,76.03 241.93,81.75 228.59,81.75 226.69,83.65 226.69,89.37 226.06,90 IO_C.25
IO_A0
  Top 0.305: IC12.10 9.52,62.7 10.79,61.43 RN1.2 IC2.18
IO_A1
  Top 0.305: IC12.12 12.06,62.7 13.33,61.43 RN1.3 IC2.17
IO_A2
  Top 0.305: IC12.14 14.6,62.7 15.87,61.43 RN1.4 IC2.16
IO_A3
  Top 0.305: IC12.16 17.14,62.7 18.41,61.43 RN1.5 IC2.15
IO_A4
  Top 0.305: IC13.10 RN1.6 IC2.14
IO_A5
  Top 0.305: IC13.12 RN1.7 IC2.13
IO_A6
  Top 0.305: IC13.14 RN1.8 IC2.12
IO_A7
  Top 0.305: IC13.16 RN1.9 IC2.11
IO_A8
  Top 0.305: IC14.10 36.19,62.7 37.46,61.43 RN2.2 IC3.18
IO_A9
  Top 0.305: IC14.12 38.73,62.7 40,61.43 RN2.3 IC3.17
IO_A10
  Top 0.305: IC14.14 41.27,62.7 42.54,61.43 RN2.4 IC3.16
IO_A11
  Top 0.305: IC14.16 43.81,62.7 45.08,61.43 RN2.5 IC3.15
IO_A12
  Top 0.305: IC15.10 RN2.6 IC3.14
IO_A13
  Top 0.305: IC15.12 RN2.7 IC3.13
IO_A14
  Top 0.305: IC15.14 RN2.8 IC3.12
IO_A15
  Top 0.305: IC15.16 RN2.9 IC3.11
IO_A16
  Top 0.305: IC16.10 62.86,62.7 64.13,61.43 RN3.2 IC4.18
IO_A17
  Top 0.305: IC16.12 65.4,62.7 66.67,61.43 RN3.3 IC4.17
IO_A18
  Top 0.305: IC16.14 67.94,62.7 69.21,61.43 RN3.4 IC4.16
IO_A19
  Top 0.305: IC16.16 70.48,62.7 71.75,61.43 RN3.5 IC4.15
IO_A20
  Top 0.305: IC17.10 RN3.6 IC4.14
IO_A21
  Top 0.305: IC17.12 RN3.7 IC4.13
IO_A22
  Top 0.305: IC17.14 RN3.8 IC4.12
IO_A23
  Top 0.305: IC17.16 RN3.9 IC4.11
IO_B0
  Top 0.305: IC5.18 RN4.2 94.61,61.43 93.34,62.7 IC18.10
IO_B1
  Top 0.305: IC5.17 RN4.3 97.15,61.43 95.88,62.7 IC18.12
IO_B2
  Top 0.305: IC5.16 RN4.4 99.69,61.43 98.42,62.7 IC18.14
IO_B3
  Top 0.305: IC5.15 RN4.5 102.23,61.43 100.96,62.7 IC18.16
IO_B4
  Top 0.305: IC5.14 RN4.6 IC19.10
IO_B5
  Top 0.305: IC5.13 RN4.7 IC19.12
IO_B6
  Top 0.305: IC5.12 RN4.8 IC19.14
IO_B7
  Top 0.305: IC5.11 RN4.9 IC19.16
IO_B8
  Top 0.305: IC6.18 RN5.2 121.28,61.43 120.01,62.7 IC20.10
IO_B9
  Top 0.305: IC6.17 RN5.3 123.82,61.43 122.55,62.7 IC20.12
IO_B10
  Top 0.305: IC6.16 RN5.4 126.36,61.43 125.09,62.7 IC20.14
IO_B11
  Top 0.305: IC6.15 RN5.5 128.9,61.43 127.63,62.7 IC20.16
IO_B12
  Top 0.305: IC6.14 RN5.6 IC21.10
IO_B13
  Top 0.305: IC6.13 RN5.7 IC21.12
IO_B14
  Top 0.305: IC6.12 RN5.8 IC21.14
IO_B15
  Top 0.305: IC6.11 RN5.9 IC21.16
IO_B16
  Top 0.305: IC22.10 146.68,62.7 147.95,61.43 RN6.2 | RN6.2 IC7.18 RN6.2
IO_B17
  Top 0.305: IC7.17 RN6.3 150.49,61.43 149.22,62.7 IC22.12
IO_B18
  Top 0.305: IC22.14 151.76,62.7 153.03,61.43 RN6.4 IC7.16
IO_B19
  Top 0.305: IC22.16 154.3,62.7 155.57,61.43 RN6.5 IC7.15
IO_B20
  Top 0.305: IC23.10 RN6.6 IC7.14
IO_B21
  Top 0.305: IC23.12 RN6.7 IC7.13
IO_B22
  Top 0.305: IC23.14 RN6.8 IC7.12
IO_B23
  Top 0.305: IC23.16 RN6.9 IC7.11
IO_C0
  Top 0.305: IC24.10 176.53,62.7 177.8,61.43 RN7.2 IC8.18
IO_C1
  Top 0.305: IC24.12 179.06,62.7 180.34,61.43 RN7.3 IC8.17
IO_C2
  Top 0.305: IC24.14 181.61,62.7 182.88,61.43 RN7.4 IC8.16
IO_C3
  Top 0.305: IC24.16 184.15,62.7 185.41,61.43 RN7.5 IC8.15
IO_C4
  Top 0.305: IC25.10 RN7.6 IC8.14
IO_C5
  Top 0.305: IC25.12 RN7.7 IC8.13
IO_C6
  Top 0.305: IC25.14 RN7.8 IC8.12
IO_C7
  Top 0.305: IC25.16 RN7.9 IC8.11
IO_C8
  Top 0.305: IC26.10 203.19,62.7 204.47,61.43 RN8.2 IC9.18
IO_C9
  Top 0.305: IC26.12 205.74,62.7 207,61.43 RN8.3 IC9.17
IO_C10
  Top 0.305: IC26.14 208.28,62.7 209.55,61.43 RN8.4 IC9.16
IO_C11
  Top 0.305: IC26.16 210.81,62.7 212.09,61.43 RN8.5 IC9.15
IO_C12
  Top 0.305: IC27.10 RN8.6 IC9.14
IO_C13
  Top 0.305: IC27.12 RN8.7 IC9.13
IO_C14
  Top 0.305: IC27.14 RN8.8 IC9.12
IO_C15
  Top 0.305: IC27.16 RN8.9 IC9.11
IO_C16
  Top 0.305: IC28.10 229.87,62.7 231.13,61.43 RN9.2 IC10.18
IO_C17
  Top 0.305: IC28.12 232.41,62.7 233.68,61.43 RN9.3 IC10.17
IO_C18
  Top 0.305: IC28.14 234.94,62.7 236.22,61.43 RN9.4 IC10.16
IO_C19
  Top 0.305: IC28.16 237.49,62.7 238.75,61.43 RN9.5 IC10.15
IO_C20
  Top 0.305: IC29.10 RN9.6 IC10.14
IO_C21
  Top 0.305: IC29.12 RN9.7 IC10.13
IO_C22
  Top 0.305: IC29.14 RN9.8 IC10.12
IO_C23
  Top 0.305: IC29.16 RN9.9 IC10.11
MON0
  Bottom 0.406: IC1.14 122.55,16.35 120.01,13.81 120.01,6.18 118.11,4.28 TRX.K
MON1
  Bottom 0.406: IC1.15 125.09,16.35 123.82,15.08 123.82,8.09 125.73,6.18 MON.K
N$1
  Top 0.305: IC12.1 R4.2
N$2
  Top 0.305: IC12.3 R3.2
N$3
  Top 0.305: IC12.5 R2.2
N$4
  Top 0.305: IC12.7 R1.2
N$5
  Top 0.305: IC13.1 R8.2
N$6
  Top 0.305: IC13.3 R7.2
N$7
  Top 0.305: IC13.5 R6.2
N$8
  Top 0.305: IC13.7 R5.2
N$9
  Top 0.305: IC14.1 R12.2
N$10
  Top 0.305: IC14.3 R11.2
N$11
  Top 0.305: IC14.5 R10.2
N$12
  Top 0.305: IC14.7 R9.2
N$13
  Top 0.305: IC15.1 R16.2
N$14
  Top 0.305: IC15.3 R15.2
N$15
  Top 0.305: IC15.5 R14.2
N$16
  Top 0.305: IC15.7 R13.2
N$17
  Top 0.305: IC16.1 R20.2
N$18
  Top 0.305: IC16.3 R19.2
N$19
  Top 0.305: IC16.5 R18.2
N$20
  Top 0.305: IC16.7 R17.2
N$21
  Top 0.305: IC17.1 R24.2
N$22
  Top 0.305: IC17.3 R23.2
N$23
  Top 0.305: IC17.5 R22.2
N$24
  Top 0.305: IC17.7 R21.2
N$25
  Top 0.305: IC18.1 100.96,72.22 R28.2
N$26
  Top 0.305: IC18.3 98.42,72.22 R27.2
N$27
  Top 0.305: IC18.5 95.88,72.22 R26.2
N$28
  Top 0.305: IC18.7 93.34,72.22 R25.2
N$29
  Top 0.305: IC19.1 R32.2
N$30
  Top 0.305: IC19.3 R31.2
N$31
  Top 0.305: IC19.5 R30.2
N$32
  Top 0.305: IC19.7 R29.2
N$33
  Top 0.305: IC20.1 R36.2
N$34
  Top 0.305: IC20.3 R35.2
N$35
  Top 0.305: IC20.5 R34.2
N$36
  Top 0.305: IC20.7 R33.2
N$37
  Top 0.305: IC21.1 R40.2
N$38
  Top 0.305: IC21.3 R39.2
N$39
  Top 0.305: IC21.5 R38.2
N$40
  Top 0.305: IC21.7 R37.2
N$41
  Top 0.305: IC22.1 R44.2
N$42
  Top 0.305: IC22.3 R43.2
N$43
  Top 0.305: IC22.5 R42.2
N$44
  Top 0.305: IC22.7 R41.2
N$45
  Top 0.305: IC23.1 R48.2
N$46
  Top 0.305: IC23.3 R47.2
N$47
  Top 0.305: IC23.5 R46.2
N$48
  Top 0.305: IC23.7 R45.2
N$49
  Top 0.305: IC24.1 R52.2
N$50
  Top 0.305: R51.2 IC24.3
N$51
  Top 0.305: IC24.5 R50.2
N$52
  Top 0.305: IC24.7 R49.2
N$53
  Top 0.305: IC25.1 R56.2
N$54
  Top 0.305: IC25.3 R55.2
N$55
  Top 0.305: IC25.5 R54.2
N$56
  Top 0.305: IC25.7 R53.2
N$57
  Top 0.305: IC26.1 R60.2
N$58
  Top 0.305: IC26.3 R59.2
N$59
  Top 0.305: IC26.5 R58.2
N$60
  Top 0.305: IC26.7 R57.2
N$61
  Top 0.305: IC27.1 R64.2
N$62
  Top 0.305: IC27.3 R63.2
N$63
  Top 0.305: IC27.5 R62.2
N$64
  Top 0.305: IC27.7 R61.2
N$65
  Top 0.305: IC28.1 R68.2
N$66
  Top 0.305: IC28.3 R67.2
N$67
  Top 0.305: IC28.5 R66.2
N$68
  Top 0.305: IC28.7 R65.2
N$69
  Top 0.305: IC29.1 R72.2
N$70
  Top 0.305: IC29.3 R71.2
N$71
  Top 0.305: IC29.5 R70.2
N$72
  Top 0.305: IC29.7 R69.2
N$73
  Bottom 0.61: R73.1 40,13.17 41.27,14.44 50.16,14.44 | 50.16,14.44 IC11.3 | XT1.6 XT1.7 XT1.2 50.16,14.44
N$74
  Bottom 0.406: IC1.18 132.71,13.81 Q1.2 C1.2
N$75
  Bottom 0.61: R74.1 36.82,14.44 38.09,15.71 43.81,15.71 45.08,16.98 IC11.1
N$76
  Bottom 0.406: IC1.19 135.25,13.81 Q1.1 C2.2
N$77
  Bottom 0.61: C16.2 163.19,25.23 165.73,22.7 IC30.6
N$78
  Bottom 0.406: TRX.A R80.1
N$79  (via drill 0.6)
  Top 0.406: v121.92,13.81 R81.1
  Bottom 0.406: v121.92,13.81 121.92,6.18 123.19,4.92 MON.A
N$80
  Bottom 0.305: SV1.4 198.12,25.23 199.38,23.96 IC31.3
N$81
  Bottom 0.305: IC31.4 196.84,27.78 SV1.3
N$82
  Bottom 0.305: SV2.4 227.96,25.23 229.23,23.96 IC32.3
N$83
  Bottom 0.305: IC32.4 226.69,27.78 SV2.3
N$103
  Bottom 0.61: IC30.1 C14.1
N$104
  Bottom 0.61: IC30.3 C14.2
N$105
  Bottom 0.61: IC30.4 C13.1
N$106
  Bottom 0.61: C13.2 167,25.87 168.27,24.6 IC30.5
N$107
  Bottom 0.61: IC30.2 175.89,27.78 182.88,27.78 C15.1
OC0  (via drill 0.6)
  Top 0.305: IC2.19 8.25,53.81 9.52,52.54 v9.52,42.38
  Bottom 0.305: v9.52,42.38 19.68,32.22 83.81,32.22 86.99,29.05 135.25,29.05 137.79,31.59 IC1.21
OC1  (via drill 0.6)
  Top 0.305: v36.19,34.76 36.19,52.54 34.92,53.81 IC3.19
  Bottom 0.305: IC1.22 135.25,31.59 133.34,29.68 87.62,29.68 83.81,33.49 37.46,33.49 v36.19,34.76
OC2  (via drill 0.6)
  Top 0.305: IC4.19 61.59,53.81 62.86,52.54 v62.86,34.76
  Bottom 0.305: v62.86,34.76 83.81,34.76 88.26,30.32 131.44,30.32 132.71,31.59 IC1.23
OC3  (via drill 0.6)
  Top 0.305: v93.34,31.59 93.34,52.54 92.07,53.81 IC5.19
  Bottom 0.305: IC1.24 130.17,31.59 129.53,30.95 93.98,30.95 v93.34,31.59
OC4
  Top 0.305: IC1.25 127.63,50 126.36,51.27 120.01,51.27 118.74,52.54 IC6.19
OC5  (via drill 0.6)
  Top 0.305: v125.09,27.78 IC1.26 | v144.14,34.76 144.14,52.54 145.41,53.81 IC7.19
  Bottom 0.305: v125.09,27.78 137.16,27.78 v144.14,34.76
OC6  (via drill 0.6)
  Top 0.305: v122.55,27.78 IC1.27 | v173.99,34.76 173.99,52.54 175.25,53.81 IC8.19
  Bottom 0.305: v122.55,27.78 123.82,26.51 137.79,26.51 146.05,34.76 v173.99,34.76
OC7  (via drill 0.6)
  Top 0.305: v120.01,27.78 IC1.28 | v200.66,34.76 200.66,52.54 201.93,53.81 IC9.19
  Bottom 0.305: v120.01,27.78 121.92,25.87 138.43,25.87 146.05,33.49 175.25,33.49 176.53,34.76 v200.66,34.76
OC8  (via drill 0.6)
  Top 0.305: v112.39,26.51 IC1.31 | v227.33,32.86 227.33,52.54 228.59,53.81 IC10.19
  Bottom 0.305: v112.39,26.51 119.38,26.51 120.65,25.23 139.06,25.23 146.68,32.86 v227.33,32.86
PB5
  Top 0.305: ISP1.4 RN10.4
  Bottom 0.305: IC1.6 102.23,15.71 RN10.4
PB6
  Bottom 0.305: ISP1.1 109.85,10 107.31,12.54 RN10.2 107.31,14.44 104.77,16.98 IC1.7
PB7
  Top 0.305: RN10.3 104.77,14.44 107.31,16.98 IC1.8
  Bottom 0.305: ISP1.3 RN10.3
RX0  (via drill 0.6)
  Top 0.305: 112.39,18.25 IC1.10 v112.39,24.6 | IC31.2 201.93,18.89 201.29,18.25 169.54,18.25 168.27,16.98 IC30.12
  Bottom 0.305: IC30.12 168.27,17.62 167.63,18.25 156.21,18.25 151.12,23.33 116.84,23.33 115.56,24.6 v112.39,24.6
RX0+
  Bottom 0.305: 199.38,10 IC31.12 | 199.38,10 R77.2 | SL1.4 199.38,10
RX0-  (via drill 0.6)
  Top 0.305: v201.93,11.9 v196.84,11.9
  Bottom 0.305: v196.84,11.9 IC31.11 | SL1.5 201.93,10 | 201.93,10 v201.93,11.9 | 201.93,10 R77.1
RX1  (via drill 0.6)
  Top 0.305: XR1.6 62.86,7.46 R75.2 93.34,7.46 94.61,8.73 IC1.3 | v231.77,31.59 IC32.2 | v160.02,31.59 160.02,24.6 159.38,23.96 159.38,18.89 160.65,17.62 IC30.9
  Bottom 0.305: IC30.9 160.65,15.71 160.02,16.35 154.3,16.35 149.22,21.43 95.25,21.43 94.61,20.79 IC1.3 94.61,18.25 | v231.77,31.59 226.06,31.59 225.42,32.22 160.65,32.22 v160.02,31.59
RX1+
  Bottom 0.305: 229.23,10 R79.2 | 229.23,10 IC32.12 | SL2.4 229.23,10
RX1-  (via drill 0.6)
  Top 0.305: v231.77,11.9 v226.69,11.9
  Bottom 0.305: v226.69,11.9 IC32.11 | SL2.5 231.77,10 | 231.77,10 v231.77,11.9 | 231.77,10 R79.1
TC0  (via drill 0.6)
  Top 0.305: 117.47,18.25 IC1.12 v117.47,24.6
  Bottom 0.305: SV1.5 SV1.6 SV1.5 | SV1.5 145.41,29.05 140.33,23.96 118.11,23.96 v117.47,24.6
TC1  (via drill 0.6)
  Top 0.305: 120.01,18.25 IC1.13 120.01,23.96 v118.74,25.23
  Bottom 0.305: SV2.5 SV2.6 SV2.5 | SV2.5 215.26,29.05 213.99,30.32 194.31,30.32 193.67,29.68 144.78,29.68 139.69,24.6 119.38,24.6 v118.74,25.23
TX0  (via drill 0.6)
  Top 0.305: 114.93,18.25 IC1.11 v114.93,23.33 | IC31.5 194.31,19.52 193.67,18.89 167,18.89 165.73,17.62 IC30.11
  Bottom 0.305: IC30.11 165.73,16.98 165.09,17.62 155.57,17.62 150.49,22.7 115.56,22.7 v114.93,23.33
TX0+
  Top 0.305: IC30.14 173.35,11.27 174.62,10 R76.2
  Bottom 0.305: 191.77,10 IC31.9 | R76.2 191.77,10 | 191.77,10 SL1.1
TX0-
  Top 0.305: IC30.13 170.81,11.9 173.99,8.73 192.4,8.73 193.67,10 R76.1
  Bottom 0.305: 194.31,10 IC31.10 | R76.1 194.31,10 | 194.31,10 SL1.2
TX1  (via drill 0.6)
  Top 0.305: v47.62,23.33 IC11.2 | v97.15,23.33 IC1.4 | v224.15,30.95 IC32.5 | v161.92,30.95 161.92,18.89 163.19,17.62 IC30.10
  Bottom 0.305: v47.62,23.33 v97.15,23.33 111.12,23.33 112.39,22.06 149.86,22.06 154.94,16.98 162.56,16.98 163.19,16.35 IC30.10 | v224.15,30.95 v161.92,30.95
TX1+
  Top 0.305: R78.2 215.26,8.09 214.62,7.46 165.73,7.46 164.46,8.73 164.46,17.62 163.19,18.89 IC30.7
  Bottom 0.305: R78.2 221.61,10 | 221.61,10 IC32.9 | 221.61,10 SL2.1
TX1-
  Top 0.305: IC30.8 160.65,18.89 161.92,17.62 161.92,8.09 163.19,6.82 223.52,6.82 224.15,6.18 SL2.2
  Bottom 0.305: SL2.2 224.15,10 | 224.15,10 IC32.10 | 224.15,10 R78.1
VCC  (via drill 0.6)
  Top 0.305: RN3.1 60.32,59.52 59.05,58.26 IC4.20 | RN2.1 33.65,59.52 32.38,58.26 IC3.20 | RN1.1 6.98,59.52 5.71,58.26 IC2.20 | RN4.1 90.8,59.52 89.53,58.26 IC5.20 | RN5.1 117.47,59.52 116.2,58.26 IC6.20 | RN6.1 144.14,59.52 142.87,58.26 IC7.20 | RN7.1 173.99,59.52 172.72,58.26 IC8.20 | RN8.1 200.66,59.52 199.38,58.26 IC9.20 | RN9.1 227.33,59.52 226.06,58.26 IC10.20 | 71.75,26.51 89.53,26.51 | ISP1.2 107.31,10 109.85,12.54 RN10.1
  Top 0.406: R81.2 125.73,15.08 125.09,15.71 v113.66,15.71
  Top 1.016: XR1.2 64.13,13.17 C8.1 | IC1.40 89.53,26.51 C7.1 71.75,26.51 | 71.75,26.51 71.75,27.78 70.48,29.05 45.71,29.05 45.08,28.41 IC11.8 C9.1 36.82,25.87 R74.2 R73.2 | 71.75,26.51 R75.1 | v23.49,4.92 v23.49,17.62 23.49,24.6 3.81,44.29 3.81,55.08 4.44,55.72 IC2.20 | v213.36,16.98 213.36,29.05 SV1.1 200.66,31.59 197.48,34.76 197.48,51.91 199.38,53.81 IC9.20
  Bottom 0.406: R81.2 R80.2 | v113.66,15.71 113.66,14.44 112.39,13.17 RN10.1
  Bottom 1.016: R75.1 71.12,17.62 | 71.12,17.62 63.49,17.62 62.86,16.98 C8.1 | C3.1 2.54,53.18 5.71,53.18 | 5.71,53.18 IC2.20 | 32.38,53.18 5.71,53.18 | 32.38,53.18 IC3.20 | 59.05,53.18 32.38,53.18 | 59.05,53.18 IC4.20 | 85.72,53.18 59.05,53.18 | 89.53,53.18 85.72,53.18 | 89.53,53.18 IC5.20 | 85.72,53.18 C4.1 | 116.2,53.18 89.53,53.18 | 116.2,53.18 IC6.20 | 142.87,53.18 116.2,53.18 | 142.87,53.18 IC7.20 | 169.54,53.18 142.87,53.18 | 172.72,53.18 169.54,53.18 | 172.72,53.18 IC8.20 | 169.54,53.18 C5.1 | 199.38,53.18 172.72,53.18 | IC9.20 199.38,53.18 | 199.38,53.18 226.06,53.18 | 226.06,53.18 IC10.20 | 226.06,53.18 252.09,53.18 C6.1 | 71.12,17.62 79.37,17.62 81.28,15.71 81.28,10 85.72,5.55 106.04,5.55 107.31,6.82 ISP1.2 | v23.49,17.62 R74.2 | v23.49,4.92 X2.1 | 234.31,16.98 240.03,16.98 C12.1 243.2,15.71 243.2,29.05 SV2.1 | 234.31,16.98 IC32.14 | 234.31,16.98 v213.36,16.98 209.55,16.98 | 209.55,16.98 C11.1 | 209.55,16.98 204.47,16.98 | 204.47,16.98 IC31.14 | 204.47,16.98 C15.2 178.43,16.98 IC30.16 C10.1

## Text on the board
tPlace: FIBER OPTIC TRANSMITTER | YONGJIN ELEC. | 2006,03 REV.B
tNames: + | - | + | -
